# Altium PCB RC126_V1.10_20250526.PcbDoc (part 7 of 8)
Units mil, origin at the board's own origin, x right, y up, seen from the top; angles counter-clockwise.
Board outline 6299.62 x 3544.12 mil, 4 copper layers (Top, GND, Power, Bottom), stack 35.4 mil thick; 509 components, 417 nets, 1867 pads, 2150 vias.
Unrouted connection lines stored in the file: 1451.
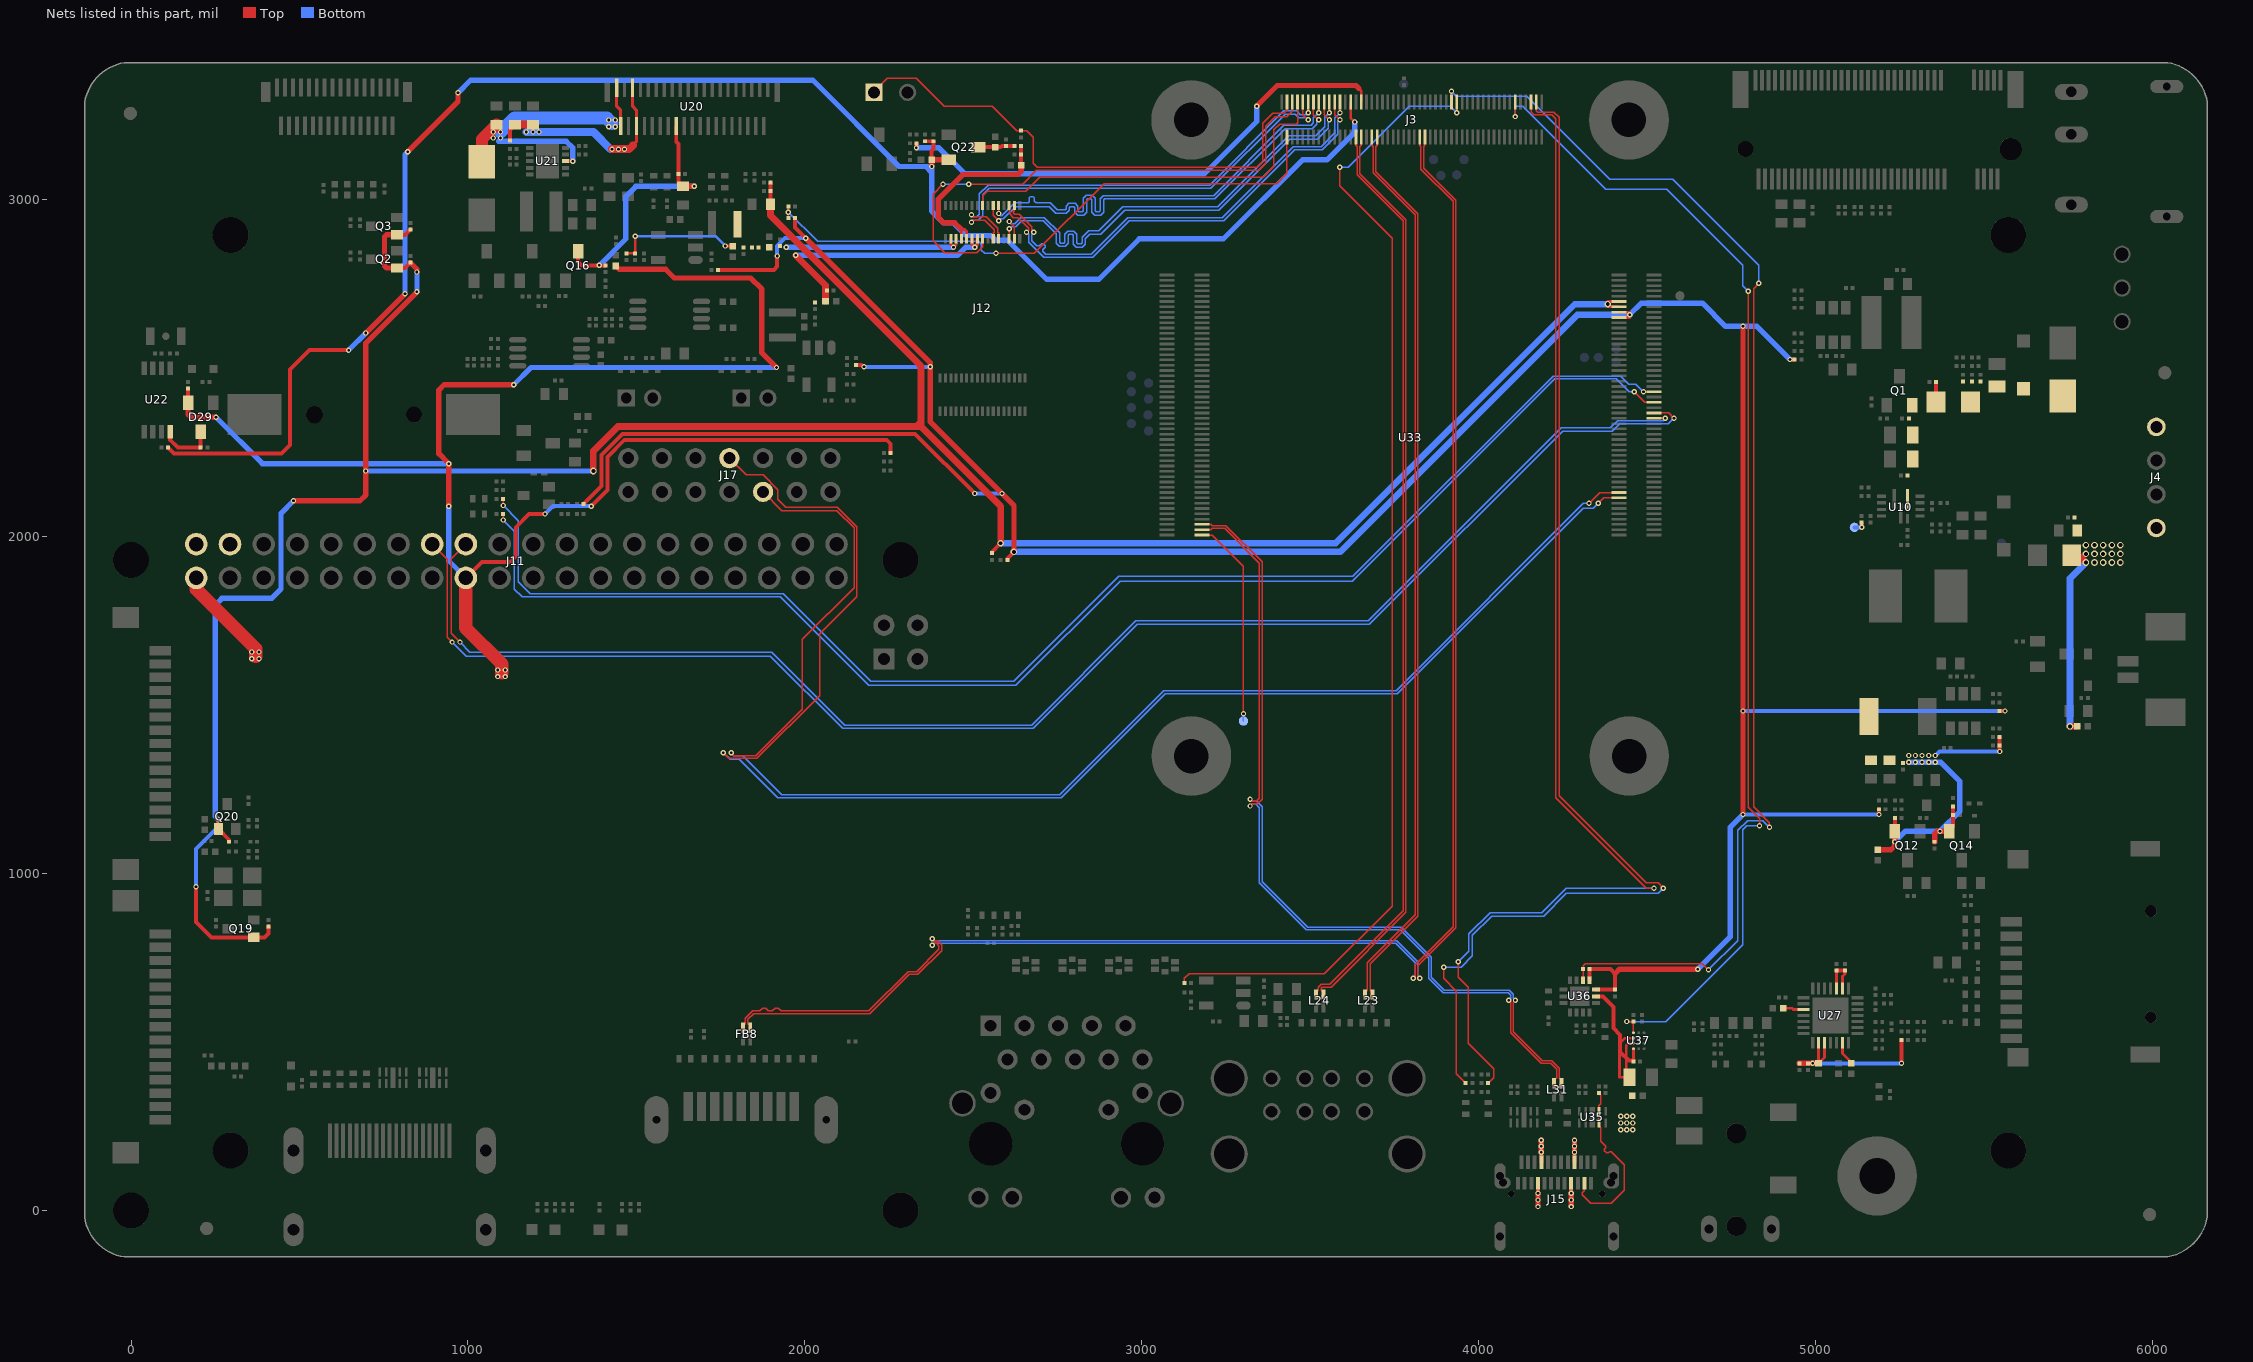
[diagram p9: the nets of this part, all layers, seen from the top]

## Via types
v1: diameter 15.75, hole 7.87, Top to Bottom, 2047 vias
v2: diameter 19.68, hole 11.81, Top to Bottom, 103 vias

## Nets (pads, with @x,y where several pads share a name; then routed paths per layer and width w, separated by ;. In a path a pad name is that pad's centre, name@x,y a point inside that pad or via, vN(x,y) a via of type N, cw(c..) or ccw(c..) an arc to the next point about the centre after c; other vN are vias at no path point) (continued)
TYPEC0TX2P: C254.2 J15.B2 U35.4 U35.7 | length 528.1
  Top w3.94: J15.B2@4312.99,80.71 4312.99,59.06 4307.09,53.15 4307.09,46.57 4332,21.65 4392.41,21.65 4431.1,60.35 4431.1,136.5 4392.63,174.98 4387.52,174.98 4383.5,170.96 4379.32,170.96 4372.36,177.92 4372.36,182.09 4376.85,186.58 4376.85,190.76 4362.2,205.4 4362.2,245.08 4356.29,250.99 U35.4@4356.29,260.34 U35.7@4356.29,294.78 4356.29,311.02 4362.2,316.93 4362.2,342.52 C254.2@4356.3,348.43
TYPEC5V_PWREN_H: J3.11 R355.1 U37.D3 | length 3514.4
  Top w3.94: v1(4107.48,3246.46) 4107.48,3279.1 J3.11@4107.48,3289.77 ; v1(4438.98,561.02) R355.1@4458.66,561.02 U37.D3@4458.66,527.56 ; v1(4799.21,2728.35) 4799.21,1196.85 4832.68,1163.39 v1(4832.68,1141.73)
  Bottom w3.94: v1(4107.48,3246.46) 4107.48,3273.62 4111.42,3277.56 4129.92,3277.56 4375.98,3031.5 4557.09,3031.5 4783.46,2805.12 4783.46,2744.09 v1(4799.21,2728.35) ; v1(4438.98,561.02) 4555.12,561.02 4783.46,789.37 4783.46,1129.92 4795.28,1141.73 v1(4832.68,1141.73)
TYPEC_DPTX_AUX_PUPDCTL1: J3.5 R338.1 | length 3640.9
  Top w3.94: v1(3938.98,738.19) 3938.98,692.91 3968.5,663.39 3968.5,496.06 4043.31,421.26 4043.31,393.7 R338.1@4027.56,377.95 ; J3.5@4154.72,3279.5 4154.72,3259.84 4162.6,3251.97 4216.54,3251.97 4228.35,3240.16 4228.35,1224.41 4496.06,956.69 v1(4519.68,956.69) ; J3.5@4154.73,3279.5 J3.5@4154.73,3289.77
  Bottom w3.94: v1(3938.98,738.19) 3970.47,769.69 3970.47,820.87 4033.46,883.86 4187.01,883.86 4259.84,956.69 v1(4519.68,956.69)
TYPEC_DPTX_AUX_PUPDCTL2: J3.3 R339.1 | length 3693.8
  Top w3.94: v1(3895.67,722.44) 3895.67,688.98 3933.07,651.57 3933.07,405.51 R339.1@3960.63,377.95 ; J3.3@4170.47,3279.9 4170.47,3263.78 4174.41,3259.84 4222.44,3259.84 4238.19,3244.09 4238.19,1230.32 4496.06,972.44 4531.5,972.44 v1(4547.24,956.69) ; J3.3@4170.48,3279.9 J3.3@4170.48,3289.77
  Bottom w3.94: v1(3895.67,722.44) 3946.85,722.44 3980.32,755.91 3980.32,816.93 4037.4,874.02 4192.91,874.02 4259.84,940.94 4531.5,940.94 v1(4547.24,956.69)
UART0_RX_M0_DEBUG: R274.2 U33.51 | length 4142.5
  Top w3.94: v1(1104.33,2049.21) R274.2@1104.33,2066.93 ; v1(4461.02,2429.92) 4492.52,2398.43 U33.51@4520.08,2398.43
  Bottom w3.94: v1(1104.33,2049.21) 1137.8,2015.75 1137.8,1844.49 1161.42,1820.87 1927.17,1820.87 2188.98,1559.06 2625.98,1559.06 2935.04,1868.11 3624.02,1868.11 4224.41,2468.5 4407.48,2468.5 4446.06,2429.92 v1(4461.02,2429.92)
UART0_TX_M0_DEBUG: R273.2 U33.55 | length 4152
  Top w3.94: v1(1104.33,2092.52) R273.2@1104.33,2112.2 ; v1(4488.19,2429.92) U33.55@4520.08,2429.92
  Bottom w3.94: v1(1104.33,2092.52) 1149.61,2047.24 1149.61,1865.98 1184.87,1830.71 1935.04,1830.71 2194.88,1570.87 2620.08,1570.87 2931.1,1881.89 3626.27,1881.89 4220.76,2476.38 4420.43,2476.38 4444.05,2452.76 4465.35,2452.76 v1(4488.19,2429.92)
UART5_RX_M0_1V8: J17.8 U33.16 | length 4476.2
  Top w3.94: v1(1757.87,1358.27) 1773.62,1342.52 1857.59,1342.52 2043.31,1528.23 2043.31,1711.92 2153.54,1822.16 2153.54,2028.85 2095.78,2086.61 1943.59,2086.61 1919.29,2110.91 1919.29,2139.75 1875.97,2183.07 1825.2,2183.07 J17.8@1775.59,2232.68 ; v1(4354.33,2099.21) 4370.08,2114.96 U33.16@4415.35,2114.96
  Bottom w3.94: v1(1757.87,1358.27) 1777.56,1338.58 1805.12,1338.58 1919.29,1224.41 2759.84,1224.41 3068.9,1533.46 3757.87,1533.46 4309.06,2084.65 4339.76,2084.65 v1(4354.33,2099.21)
UART5_TX_M0_1V8: J17.9 U33.18 | length 4243
  Top w3.94: v1(1781.5,1358.27) 1789.37,1350.39 1854.33,1350.39 1992.13,1488.19 1992.13,1694.88 2145.67,1848.43 2145.67,2025.59 2094.49,2076.77 1931.5,2076.77 J17.9@1875.59,2132.68 ; v1(4326.77,2099.21) 4358.27,2130.71 U33.18@4415.35,2130.71
  Bottom w3.94: v1(1781.5,1358.27) 1789.37,1350.39 1814.96,1350.39 1931.1,1234.25 2755.91,1234.25 3064.96,1543.31 3753.94,1543.31 4309.84,2099.21 v1(4326.77,2099.21)
UART7_RX_M0: J11.18 U33.45 | length 4407.7
  Top w3.94: v1(976.38,1687.01) 950.79,1712.6 950.79,1934.65 J11.18@993.7,1977.56 ; U33.45@4520.08,2351.18 v1(4553.15,2351.18)
  Bottom w3.94: v1(976.38,1687.01) 1005.91,1657.48 1901.57,1657.48 2118.11,1440.94 2673.23,1440.94 2982.28,1750 3671.26,1750 4244.09,2322.83 4389.76,2322.83 4411.42,2344.49 4546.46,2344.49 v1(4553.15,2351.18)
UART7_TX_M0: J11.16 U33.47 | length 4493.3
  Top w3.94: J11.16@893.7,1977.56 938.98,1932.28 938.98,1700.79 v1(952.76,1687.01) ; U33.47@4520.08,2366.93 4562.99,2366.93 v1(4578.74,2351.18)
  Bottom w3.94: v1(952.76,1687.01) 994.09,1645.67 1897.64,1645.67 2112.2,1431.1 2677.17,1431.1 2986.22,1740.16 3675.2,1740.16 4248.03,2312.99 4395.67,2312.99 4417.32,2334.65 4562.2,2334.65 v1(4578.74,2351.18)
UFS_FSPI_PLUG: J2.1 J3.97 R15.1 | length 1558.8
  Top w3.94: J2.1@2204.72,3318.5 2204.72,3320.87 2244.09,3360.24 2330.71,3360.24 2413.39,3277.56 2555.12,3277.56 2627.95,3204.72 R15.1@2641.73,3204.72 2657.48,3204.72 2677.17,3185.04 2677.17,3108.27 2688.98,3096.46 3340.55,3096.46 3358.27,3114.17 3358.27,3226.38 3387.8,3255.91 3421.26,3255.91 3430.32,3264.96 3430.32,3279.8 J3.97@3430.32,3289.77
UFS_REFCLK: J3.93 J12.42 | length 1178.7
  Top w3.94: J12.42@2527.17,2982.28 2527.17,3011.81 2540.94,3025.59 2655.51,3025.59 2696.85,3066.93 3360.24,3066.93 3391.73,3098.43 3391.73,3206.69 3409.45,3224.41 3457.87,3224.41 3461.81,3228.35 3461.81,3279.8 J3.93@3461.82,3289.77
UFS_RSTN: J3.95 J12.57 | length 1591.5
  Top w3.94: v1(2409.45,3045.28) 2379.92,3015.75 2379.92,2877.95 2415.35,2842.52 2509.84,2842.52 2527.17,2859.84 J12.57@2527.17,2883.86 ; v1(2486.22,3045.28) 2645.67,3045.28 2687.01,3086.61 3346.46,3086.61 3368.11,3108.27 3368.11,3218.5 3395.67,3246.06 3430.32,3246.06 3446.06,3261.81 3446.06,3278.3 J3.95@3446.07,3289.77
  Bottom w3.94: v1(2409.45,3045.28) v1(2486.22,3045.28)
UFS_RX_D0N: J3.83 J12.62 | length 1334.3
  Top w3.94: J12.62@2605.91,2883.86 2605.91,2913.39 v1(2606.3,2913.39) ; J3.83@3540.56,3289.77 3540.55,3252.36 v1(3556.3,3236.61)
  Bottom w3.94: v1(2606.3,2913.39) 2612.2,2919.29 2625.98,2919.29 2643.7,2937.01 2706.69,2937.01 2745.6,2898.11 2745.6,2869.94 2754.31,2861.22 2772.31,2861.22 2781.03,2869.94 2781.03,2893.7 2783.98,2896.65 2793.82,2896.65 2796.78,2893.7 2796.78,2867.97 2805.49,2859.25 2823.49,2859.25 2832.21,2867.97 2832.21,2883.86 2845.47,2897.12 2877.44,2897.12 2948.82,2968.5 3228.49,2968.5 3439.12,3179.13 3519.69,3179.13 3552.17,3211.61 3552.17,3232.48 v1(3556.3,3236.61)
UFS_RX_D0P: J3.81 J12.63 | length 1343.1
  Top w3.94: v1(2606.3,2935.04) 2621.65,2919.69 J12.63@2621.65,2883.86 ; v1(3556.3,3258.27) J3.81@3556.3,3289.77
  Bottom w3.94: v1(2606.3,2935.04) 2612.2,2929.13 2621.91,2929.13 2639.62,2946.85 2639.76,2946.85 2710.77,2946.85 2755.44,2902.18 2755.44,2874.02 2758.39,2871.06 2768.23,2871.06 2771.19,2874.02 2771.19,2897.78 2779.9,2906.5 2797.9,2906.5 2806.62,2897.78 2806.62,2872.05 2809.57,2869.09 2819.41,2869.09 2822.37,2872.05 2822.37,2887.94 2841.4,2906.96 2871.53,2906.96 2942.91,2978.35 3224.41,2978.35 3435.04,3188.98 3515.61,3188.98 3542.32,3215.69 3542.32,3244.29 v1(3556.3,3258.27)
UFS_RX_D1N: J3.91 J12.59 | length 1344.8
  Top w3.94: v1(2494.09,2933.07) 2500,2938.98 2533.92,2938.98 2561.61,2911.28 2561.61,2902.56 2558.66,2899.61 J12.59@2558.66,2883.86 ; J3.91@3477.56,3289.77 3477.56,3252.36 v1(3493.31,3236.61)
  Bottom w3.94: v1(2494.09,2933.07) 2500,2938.98 2513.78,2938.98 2527.56,2952.76 2527.56,3013.78 2547.24,3033.46 3204.86,3033.46 3425.34,3253.94 3454.58,3253.94 3466,3242.52 3487.4,3242.52 v1(3493.31,3236.61)
UFS_RX_D1P: J3.89 J12.60 | length 1332.9
  Top w3.94: v1(2494.09,2954.72) 2500,2948.82 2537.99,2948.82 2571.46,2915.35 2571.46,2902.56 2574.41,2899.61 J12.60@2574.41,2883.86 ; v1(3493.31,3258.27) J3.89@3493.31,3289.77
  Bottom w3.94: v1(2494.09,2954.72) 2500,2948.82 2509.7,2948.82 2517.72,2956.83 2517.72,3015.75 2517.72,3017.86 2543.17,3043.31 3200.79,3043.31 3421.26,3263.78 3458.66,3263.78 3470.08,3252.36 3487.4,3252.36 v1(3493.31,3258.27)
UFS_TX_D0N: J3.79 J12.37 | length 1337.9
  Top w3.94: J12.37@2605.91,2982.28 2605.91,2966.54 2608.86,2963.58 2608.86,2956.69 2618.7,2946.85 2631.75,2946.85 2663.39,2915.21 2663.39,2909.45 v1(2657.48,2903.54) ; J3.79@3572.05,3289.76 3572.05,3252.36 v1(3587.8,3236.61)
  Bottom w3.94: v1(2657.48,2903.54) 2663.39,2897.64 2663.39,2873.88 2708.52,2828.74 2853.42,2828.74 2961.68,2937.01 3242.27,2937.01 3452.9,3147.64 3535.43,3147.64 3581.69,3193.9 3581.69,3230.51 v1(3587.8,3236.61)
UFS_TX_D0P: J3.77 J12.36 | length 1327.9
  Top w3.94: J12.36@2621.65,2982.28 2621.65,2966.54 2618.7,2963.58 2618.7,2960.77 2622.78,2956.69 2635.83,2956.69 2673.23,2919.29 2673.23,2909.45 v1(2679.13,2903.54) ; v1(3587.8,3258.27) J3.77@3587.8,3289.77
  Bottom w3.94: v1(2679.13,2903.54) 2673.23,2897.64 2673.23,2877.95 2688.01,2863.17 2695.91,2863.17 2702.4,2869.66 2706.57,2869.66 2713.53,2862.7 2713.53,2858.53 2706.17,2851.16 2706.17,2846.98 2714.57,2838.58 2849.34,2838.58 2957.61,2946.85 3238.19,2946.85 3448.82,3157.48 3531.36,3157.48 3571.85,3197.97 3571.85,3242.32 v1(3587.8,3258.27)
UFS_TX_D1N: J3.87 J12.40 | length 1346.4
  Top w3.94: J12.40@2558.66,2982.28 2558.66,2953.15 v1(2574.8,2937.01) ; J3.87@3509.06,3289.77 3509.06,3252.36 v1(3524.8,3236.61)
  Bottom w3.94: v1(2574.8,2937.01) 2580.71,2942.91 2588.58,2942.91 2625,2979.33 2724.34,2979.33 2744.02,2959.65 2775.73,2959.65 2784.45,2968.36 2784.45,2976.38 2787.4,2979.33 2797.24,2979.33 2800.2,2976.38 2800.2,2962.46 2808.92,2953.74 2826.91,2953.74 2835.63,2962.46 2835.63,3000 2838.58,3002.95 2848.43,3002.95 2851.38,3000 2851.38,2962.46 2860.1,2953.74 2878.09,2953.74 2886.81,2962.46 2886.81,2999.02 2889.76,3001.97 3216.68,3001.97 3425.34,3210.63 3505.91,3210.63 3518.7,3223.43 3518.7,3230.51 v1(3524.8,3236.61)
UFS_TX_D1P: J3.85 J12.39 | length 1330.7
  Top w3.94: J12.39@2574.41,2982.28 2574.8,2981.89 v1(2574.8,2958.66) ; v1(3524.8,3258.27) J3.85@3524.81,3289.77
  Bottom w3.94: v1(2574.8,2958.66) 2580.71,2952.76 2584.51,2952.76 2621.91,2990.16 2662.4,2990.16 2665.35,2993.11 2665.35,3006.34 2668.31,3009.29 2678.15,3009.29 2681.1,3006.34 2681.1,2994.65 2685.59,2990.16 2727.43,2990.16 2748.1,2969.49 2771.65,2969.49 2774.61,2972.44 2774.61,2980.45 2783.32,2989.17 2801.32,2989.17 2810.04,2980.45 2810.04,2966.54 2812.99,2963.58 2822.83,2963.58 2825.79,2966.54 2825.79,3004.08 2834.51,3012.8 2852.5,3012.8 2861.22,3004.08 2861.22,2966.54 2864.17,2963.58 2874.02,2963.58 2876.97,2966.54 2876.97,3003.09 2885.69,3011.81 3212.6,3011.81 3421.26,3220.47 3501.83,3220.47 3508.86,3227.5 3508.86,3242.32 v1(3524.8,3258.27)
USB2_OTG0_DM: L31.4 R343.1 U33.103 | length 2487.2
  Top w3.94: U33.103@3178.74,2020.47 3204.72,2020.47 3208.66,2024.41 3245.61,2024.41 3348.43,1921.6 3348.43,1223.73 3339.26,1214.57 3326.77,1214.57 v1(3320.87,1220.47) ; v1(4108.27,624.02) 4102.36,618.11 4102.36,530.82 4188.3,444.88 4215.86,444.88 4238.19,422.55 4238.19,394.69 4245.08,387.8 L31.4@4245.08,382.88 4244.09,382.88 R343.1@4244.09,368.11
  Bottom w3.94: v1(3320.87,1220.47) 3326.77,1214.57 3340.55,1214.57 3356.3,1198.82 3356.3,975.7 3491.45,840.55 3769.68,840.55 3858.27,751.97 3858.27,692.24 3896.96,653.54 4090.55,653.54 4102.36,641.73 4102.36,629.92 v1(4108.27,624.02)
USB2_OTG0_DP: L31.3 R345.1 U33.105 | length 2499.7
  Top w3.94: U33.105@3178.74,2036.22 3204.72,2036.22 3208.66,2032.28 3248.87,2032.28 3356.3,1924.86 3356.3,1220.47 3342.52,1206.69 3326.77,1206.69 v1(3320.87,1200.79) ; v1(4088.58,624.02) 4094.49,618.11 4094.49,527.56 4185.04,437.01 4212.6,437.01 4230.32,419.29 4230.32,394.69 4223.42,387.8 L31.3@4223.42,382.88 4224.41,381.89 R345.1@4224.41,368.11
  Bottom w3.94: v1(3320.87,1200.79) 3326.77,1206.69 3337.29,1206.69 3348.43,1195.56 3348.43,972.44 3488.19,832.68 3766.42,832.68 3850.39,748.71 3850.39,688.98 3893.7,645.67 4087.29,645.67 4094.49,638.47 4094.49,629.92 v1(4088.58,624.02)
USB2_OTG0_ID: P14.1 U33.101 | length 620
  Top w3.94: U33.101@3178.74,2004.72 3208.27,2004.72 3301.18,1911.81 v1(3301.18,1474.41)
  Bottom w3.94: P14.1@3301.18,1452.76 v1(3301.18,1474.41)
USB2_OTG0_VBUSDET: J3.98 R3.1 R4.1 | length 1782.1
  Top w3.94: R3.1@1950.79,2944.88 v1(1950.79,2962.6) R4.1@1950.79,2980.32 ; v1(2566.93,2840.55) 2681.1,2840.55 2887.8,3047.24 3399.61,3047.24 3430.32,3077.95 3430.32,3181 J3.98@3430.32,3185.83
  Bottom w3.94: v1(1950.79,2962.6) 2037.4,2875.98 2515.75,2875.98 2523.62,2868.11 2523.62,2850.39 2533.46,2840.55 v1(2566.93,2840.55)
USB20_1DM: FB8.1 J3.48 R282.2 | length 4844.1
  Top w3.94: R282.2@1816.93,533.46 1816.93,547.24 FB8.1@1815.94,548.23 1822.83,555.12 1822.83,570.53 1844.83,592.52 1866.14,592.52 1874.02,600.39 1883.86,600.39 1891.73,592.52 1903.54,592.52 1911.42,600.39 1921.26,600.39 1929.13,592.52 2189.65,592.52 2305.79,708.66 2331.38,708.66 2397.64,774.92 2397.64,786.11 2390.44,793.31 2383.86,793.31 v1(2377.95,787.4) ; v1(3805.12,688.98) 3811.02,694.88 3811.02,730.19 3923.23,842.4 3923.23,2994.77 3827.95,3090.05 3827.95,3157.48 3824.02,3161.42 3824.02,3180.9 J3.48@3824.02,3185.83
  Bottom w3.94: v1(2377.95,787.4) 2383.86,793.31 3752.64,793.31 3811.02,734.93 3811.02,694.88 v1(3805.12,688.98)
USB20_1DP: FB8.2 J3.46 R283.2 | length 4857.2
  Top w3.94: R283.2@1836.61,533.46 1836.61,547.24 FB8.2@1837.6,548.23 1830.71,555.12 1830.71,567.27 1848.09,584.65 2192.91,584.65 2309.06,700.79 2334.65,700.79 2405.51,771.65 2405.51,789.37 2393.7,801.18 2383.86,801.18 v1(2377.95,807.09) ; v1(3824.8,688.98) 3818.9,694.88 3818.9,726.93 3931.1,839.14 3931.1,2998.03 3835.83,3093.31 3835.83,3157.48 3839.76,3161.42 3839.76,3178 J3.46@3839.77,3185.83
  Bottom w3.94: v1(2377.95,807.09) 2383.86,801.18 3755.91,801.18 3818.9,738.19 3818.9,694.88 v1(3824.8,688.98)
USB20_2DM: J3.66 L23.1 R299.1 | length 2669.8
  Top w3.94: R299.1@3663.39,631.89 3663.39,646.66 L23.1@3662.4,646.66 3669.29,653.55 3669.29,735.54 3811.02,877.28 3811.02,2954.72 3686.22,3079.53 3686.22,3157.48 3682.28,3161.42 3682.28,3179.9 J3.66@3682.29,3185.83
USB20_2DP: J3.64 L23.2 R301.1 | length 2669.2
  Top w3.94: R301.1@3683.07,631.89 3683.07,645.67 L23.2@3684.06,646.66 3677.17,653.55 3677.17,732.28 3818.9,874.02 3818.9,2957.99 3694.09,3082.79 3694.09,3157.48 3698.03,3161.42 3698.03,3179.6 J3.64@3698.04,3185.83
USB20_3DM: J3.72 L24.1 R300.1 | length 2735.4
  Top w3.94: R300.1@3517.72,631.89 3517.72,646.66 L24.1@3516.73,646.66 3523.62,653.55 3523.62,661.42 3523.62,662.71 3532.17,671.26 3533.46,671.26 3557.76,671.26 3775.59,889.09 3775.59,2937.01 3638.98,3073.62 3638.98,3157.48 3635.04,3161.42 3635.04,3179.3 J3.72@3635.04,3185.83
USB20_3DP: J3.70 L24.2 R302.1 | length 2734.8
  Top w3.94: R302.1@3537.4,631.89 3537.4,645.67 L24.2@3538.39,646.66 3531.5,653.55 3531.5,659.45 3535.43,663.39 3561.02,663.39 3783.46,885.83 3783.46,2940.27 3646.85,3076.88 3646.85,3157.48 3650.79,3161.42 3650.79,3176.7 J3.70@3650.79,3185.83
USB_PWR_EN: J3.33 R279.2 | length 3438.3
  Top w3.94: R279.2@3125.98,675.2 3125.98,688.98 3139.76,702.76 3541.34,702.76 3742.13,903.54 3742.13,2885.83 3586.61,3041.34 v1(3586.61,3096.46) ; v1(3934.25,3258.27) 3934.25,3278.5 J3.33@3934.26,3289.77
  Bottom w3.94: v1(3586.61,3096.46) 3612.2,3096.46 3793.31,3277.56 3914.96,3277.56 v1(3934.25,3258.27)
USBCC_INT_L: J3.35 R351.2 U36.5 | length 3839.8
  Top w3.94: J3.35@3918.51,3289.77 3918.51,3300.8 v1(3918.5,3321.26) ; U36.5@4309.06,683.46 R351.2@4309.06,716.54 4309.06,726.38 4314.96,732.28 4663.39,732.28 v1(4681.1,714.57) ; v1(4830.71,2751.97) 4814.96,2736.22 4814.96,1198.82 4862.2,1151.57 v1(4862.2,1137.8)
  Bottom w3.94: v1(3918.5,3321.26) 3932.68,3307.09 4141.73,3307.09 4387.8,3061.02 4574.8,3061.02 4830.71,2805.12 v1(4830.71,2751.97) ; v1(4681.1,714.57) 4767.72,801.18 4767.72,1127.95 4797.24,1157.48 4842.52,1157.48 v1(4862.2,1137.8)
VBUS_TYPEC0: C256.1 J15.A4 J15.A9 J15.B4 J15.B9 R352.2 R353.1 U36.2 U37.A3 U37.B3 U37.C3 | length 863.3
  Top w7.87: R353.1@4458.66,442.91 4458.66,444.88 U37.A3@4458.66,480.32 ; U37.B3@4458.66,496.06 4442.91,496.06 4437.01,490.16 4437.01,415.35 4446.85,405.51 C256.1@4446.85,395.67 4417.32,395.67 4417.32,496.06 4433.07,511.81 U37.C3@4458.66,511.81
  Top w11.81: v1(4175.2,51.18) J15.B9@4175.2,80.71 ; J15.A4@4185.04,143.7 v1(4185.04,173.23) ; v1(4273.62,51.18) J15.B4@4273.62,80.71 ; J15.A9@4283.46,143.7 v1(4283.46,173.23) ; U36.2@4346.85,635.83 4368.11,635.83 4399.61,604.33 4399.61,541.34 4419.29,521.65 4419.29,470.47 4444.88,444.88 R353.1@4458.66,444.88
  Top w15.75: v1(4175.2,11.81) v1(4175.2,51.18) ; v1(4185.04,173.23) v1(4185.04,208.66) ; v1(4273.62,11.81) v1(4273.62,51.18) ; v1(4283.46,173.23) v1(4283.46,208.66)
  other v1: 4175.2,31.5 4273.62,31.5 4185.04,190.94 4283.46,190.94 4421.26,240.16 4438.98,240.16 4456.69,240.16 4421.26,259.84 4438.98,259.84 4456.69,259.84 4421.26,279.53 4438.98,279.53 4456.69,279.53
VCC1V2_UFS_VCCQ_S0: C237.1 C238.1 J12.51 J12.52 R328.2 | length 553.8
  Top w7.87: J12.51@2432.68,2883.86 2432.68,2866.54 v1(2440.94,2858.27) 2448.43,2865.75 J12.52@2448.43,2883.86
  Bottom w15.75: v1(1944.88,2858.27) v1(2440.94,2858.27)
VCC1V8_UFS_VCCQ2_S0: C229.1 C230.1 J12.53 J12.54 R320.2 | length 561
  Top w7.87: J12.53@2464.17,2883.86 2464.17,2911.42 2474.41,2911.42 2479.92,2905.91 J12.54@2479.92,2883.86
  Top w11.81: C229.1@2641.73,3102.36 C230.1@2641.73,3133.86 R320.2@2641.73,3159.45
  Top w15.75: 2464.17,2911.42 2444.49,2931.1 2411.42,2931.1 2395.67,2946.85 2395.67,3001.97 2468.5,3074.8 2631.89,3074.8 2641.73,3084.65 C229.1@2641.73,3102.36
VCC1V8_UFS_VCCQ2_S0_P: C209.1 C226.1 Q22.3 R320.1 | length 109.9
  Top w11.81: Q22.3@2513.78,3155.51 C209.1@2564.96,3155.51 2580.71,3155.51 2584.65,3159.45 C226.1@2596.46,3159.45 R320.1@2622.05,3159.45
VCC3V3_SYS: C156.1 C159.1 C160.1 C164.1 C173.1 D29.2 J11.1 J11.17 L15.2 Q12.2 Q14.2 R16.1 R164.2 R187.1 R206.2 R213.2 R220.2 R231.1 R254.1 | length 6563.5
  Top w3.94: v1(358.27,1637.8) 366.86,1646.39 368.11,1646.39 ; v1(358.27,1657.48) 358.27,1656.23 368.11,1646.39 ; 370.08,1644.98 372.74,1644.98 v1(379.92,1637.8) ; 370.08,1646.39 368.11,1646.39 ; 370.08,1648.62 378.93,1657.48 v1(379.92,1657.48) ; v1(1088.58,1584.65) 1089.84,1584.65 1100.39,1595.19 1100.39,1594.49 ; v1(1088.58,1604.33) 1100.39,1604.33
  Top w11.81: D29.2@169.29,2397.64 R16.1@169.29,2438.98 ; J11.17@993.7,1877.56 1041.34,1925.2 1125.98,1925.2 1141.73,1940.94 1141.73,2027.56 1181.1,2066.93 v1(1228.35,2066.93) ; v1(1366.14,2090.55) 1413.39,2137.8 1413.39,2236.22 1464.57,2287.4 2242.13,2287.4 2253.94,2275.59 R220.2@2253.94,2248.03 ; Q12.2@5234.25,1125.99 R206.2@5234.25,1165.35 ; Q14.2@5395.67,1125.99 5407.48,1137.8 R213.2@5407.48,1173.23 C173.1@5407.48,1198.82 ; v1(5545.28,1362.2) C160.1@5545.28,1379.92 R187.1@5545.28,1405.51
  Top w15.75: D29.2@169.29,2397.64 169.29,2362.2 177.17,2354.33 v1(251.97,2354.33) ; v1(942.91,2090.55) v1(942.91,2216.54) 913.39,2246.06 913.39,2435.04 929.13,2450.79 v1(1135.83,2450.79) ; R254.1@1438.98,2803.15 1448.82,2793.31 1586.61,2793.31 1612.2,2767.72 1838.58,2767.72 1872.05,2734.25 1872.05,2545.28 v1(1915.35,2501.97) ; R164.2@5183.07,1070.87 5222.44,1070.87 5234.25,1082.68 v1(5234.25,1094.49) Q12.2@5234.25,1125.99 ; R231.1@5352.36,1094.49 5352.36,1118.11 5360.24,1125.98 v1(5368.11,1125.98) Q14.2@5395.67,1125.99 Q14.2@5395.67,1114.17
  Top w39.37: J11.1@193.7,1877.56 193.7,1843.7 370.08,1667.32 370.08,1648.62 370.08,1646.39 370.08,1644.98 ; J11.17@993.7,1877.56 993.7,1728.74 1100.39,1622.05 1100.39,1604.33 1100.39,1595.19
  Bottom w11.81: v1(1228.35,2066.93) 1251.97,2090.55 v1(1366.14,2090.55) ; v1(5354.33,1350.39) 5366.14,1362.2 v1(5545.28,1362.2)
  Bottom w15.75: v1(251.97,2354.33) 389.76,2216.54 v1(942.91,2216.54) ; v1(942.91,2090.55) 942.91,1928.35 J11.17@993.7,1877.56 ; v1(1135.83,2450.79) 1187.01,2501.97 v1(1915.35,2501.97) ; v1(5234.25,1094.49) 5265.75,1125.98 v1(5368.11,1125.98) 5427.17,1185.04 5427.17,1273.62 5370.08,1330.71 v1(5354.33,1330.71) v1(5334.65,1330.71) v1(5314.96,1330.71) v1(5295.28,1330.71) v1(5275.59,1330.71)
  other v1: 5275.59,1350.39 5295.28,1350.39 5314.96,1350.39 5334.65,1350.39 1110.24,1584.65 1110.24,1604.33
VCC5V: C78.1 C79.1 FB9.1 J4.4 J11.2 J11.4 R18.2 | length 577.8
  Top w19.68: v2(5753.94,1437.01) FB9.1@5775.59,1437.01 ; R18.2@5759.84,1944.88 5779.53,1944.88 v2(5801.18,1923.23)
  Bottom w19.68: v2(5753.94,1437.01) 5753.94,1875.98 v2(5801.18,1923.23)
  other v2: 5826.77,1923.23 5852.36,1923.23 5877.95,1923.23 5903.54,1923.23 5801.18,1948.82 5826.77,1948.82 5852.36,1948.82 5877.95,1948.82 5903.54,1948.82 5801.18,1974.41 5826.77,1974.41 5852.36,1974.41 5877.95,1974.41 5903.54,1974.41
VCC12V: C83.1 C84.1 C89.1 J4.1 Q1.2 R1.1 R5.2 R17.2 U10.1 | length 59.1
  Top w11.81: R17.2@5356.3,2399.61 R1.1@5356.3,2458.66
VCC12V_DCIN: C155.1 C161.2 C162.1 D4.2 D5.2 R17.1 R176.2
VCC_1V8_S0: C178.1 C179.1 Q2.1 Q3.1 Q19.1 Q20.1 R9.2 R12.2 R212.2 R215.2 R233.1 R271.2 U33.88 U33.90 | length 8367.9
  Top w7.87: U33.88@4415.35,2681.89 4382.28,2681.89 v2(4382.28,2689.76) 4382.28,2697.64 U33.90@4415.35,2697.64
  Top w11.81: v1(192.91,960.63) 192.91,856.3 238.19,811.02 Q19.1@364.17,811.02 395.67,811.02 407.48,822.83 R212.2@407.48,842.52 ; Q20.1@259.84,1131.89 291.34,1100.4 R271.2@291.34,1094.49 ; Q2.1@789.37,2797.24 812.99,2797.24 R9.2@828.74,2812.99 ; Q3.1@789.37,2895.67 812.99,2895.67 R12.2@828.74,2911.42 ; C179.1@1897.64,2986.22 C178.1@1897.64,3025.59 R233.1@1897.64,3051.18 ; R215.2@2555.12,1950.79 2555.12,1954.72 v2(2580.71,1980.32)
  Top w15.75: Q20.1@259.84,1131.89 v1(259.84,1159.45) ; v1(482.28,2106.3) 679.13,2106.3 696.85,2124.02 v1(696.85,2194.88) 696.85,2574.8 v1(848.43,2726.38) ; Q2.1@789.37,2797.24 757.87,2797.24 751.97,2803.15 751.97,2889.76 757.87,2895.67 Q3.1@789.37,2895.67 ; R9.2@828.74,2812.99 848.43,2793.31 v1(848.43,2785.43)
  Top w19.68: v2(1372.05,2194.88) 1372.05,2253.94 1444.88,2326.77 2330.71,2326.77 ; C179.1@1897.64,2986.22 1897.64,2952.76 2344.49,2505.91 2344.49,2340.55 ; v2(2580.71,1980.32) 2580.71,2090.55 2344.49,2326.77 ; 2330.71,2326.77 2344.49,2340.55 ; 2330.71,2326.77 2344.49,2326.77 ; 2344.49,2326.77 2344.49,2340.55
  Bottom w11.81: v1(192.91,960.63) 192.91,1072.83 259.84,1139.76 v1(259.84,1159.45)
  Bottom w15.75: v1(259.84,1159.45) 250,1169.29 250,1797.24 269.69,1816.93 417.32,1816.93 444.88,1844.49 444.88,2068.9 v1(482.28,2106.3) ; v1(696.85,2194.88) v2(1372.05,2194.88) ; v1(848.43,2726.38) v1(848.43,2785.43)
  Bottom w19.68: v2(2580.71,1980.32) 3574.8,1980.32 4284.25,2689.76 v2(4382.28,2689.76)
VCC_1V8_S3: C227.1 C228.1 J3.73 Q22.2 R263.1 R321.1 | length 5152.8
  Top w3.94: J3.73@3619.3,3287.4 J3.73@3619.3,3289.77
  Top w7.87: J3.73@3619.29,3287.4 3619.29,3242.91 v1(3631.89,3230.32)
  Top w11.81: R263.1@110.24,2263.78 127.95,2246.06 446.85,2246.06 472.44,2271.65 472.44,2496.06 529.53,2553.15 v1(645.67,2553.15) ; C228.1@2356.3,3173.23 R321.1@2381.89,3173.23 2381.89,3150.59 2375.98,3144.69 C227.1@2375.98,3118.11
  Top w15.75: v1(696.85,2604.33) v1(812.99,2720.47) ; v1(820.87,3141.73) 970.47,3291.34 v1(970.47,3316.93) ; v1(2375.98,3098.43) C227.1@2375.98,3118.11 2395.67,3118.11 Q22.2@2427.16,3118.11
  Bottom w3.94: v1@2375.98,3096.46 v1(2375.98,3098.43)
  Bottom w15.75: v1(645.67,2553.15) v1(696.85,2604.33) ; v1(812.99,2720.47) 812.99,3133.86 v1(820.87,3141.73) ; v1(970.47,3316.93) 1007.87,3354.33 2023.62,3354.33 2279.53,3098.43 2358.27,3098.43 ; v1@2375.98,3096.46 2375.98,3080.71 ; v1(2375.98,3098.43) 2358.27,3098.43 ; v1(3631.89,3230.32) 3631.89,3200.79 3549.21,3118.11 3476.38,3118.11 3242.13,2883.86 2992.13,2883.86 2872.05,2763.78 2716.54,2763.78 2600.39,2879.92 2564.96,2879.92 2551.18,2893.7 2478.35,2893.7 2440.94,2931.1 2411.42,2931.1 2375.98,2966.54 2375.98,3080.71 ; 2358.27,3098.43 2375.98,3080.71
VCC_3V3_S0: C269.1 R3.2 R204.1 R214.2 R288.1 R303.1 R327.1 R331.1 R351.1 R357.1 U33.84 U33.86 U36.3 U36.4 | length 9721.1
  Top w7.87: U33.84@4415.35,2650.39 4447.24,2650.39 v1(4447.24,2658.27) 4447.24,2666.14 U33.86@4415.35,2666.14
  Top w11.81: R357.1@1342.52,2096.46 1395.67,2149.61 1395.67,2242.13 1458.66,2305.12 2326.77,2305.12 v1(2503.94,2127.95) ; R331.1@1742.13,2791.34 1907.48,2791.34 1917.32,2801.18 v1(1917.32,2832.68) ; R3.2@1970.47,2944.88 1970.47,2917.32 v1(2001.97,2885.83) ; R303.1@2151.57,2509.84 2167.32,2509.84 2173.23,2503.94 v1(2175.2,2503.94) ; R214.2@2600.39,1931.1 2600.39,1935.04 v2(2620.08,1954.72) ; U36.4@4328.74,683.46 R351.1@4328.74,716.54 4389.76,716.54 4403.54,702.76 C269.1@4403.54,655.51 U36.3@4346.85,655.51 ; v1(4923.23,2525.59) R288.1@4937.01,2525.59 ; v1(5187.01,1175.2) R327.1@5187.01,1190.94 ; R204.1@5545.28,1482.28 v1(5561.02,1482.28)
  Top w15.75: v1(2001.97,2885.83) 2372.05,2515.75 v1(2372.05,2503.94) 2372.05,2340.55 v1(2584.65,2127.95) 2620.08,2092.52 v2(2620.08,1954.72) ; 4403.54,702.76 4417.32,716.54 v1(4649.61,716.54) ; v1(4783.46,1175.2) v1(4783.46,1482.28) v1(4783.46,2624.02)
  Bottom w11.81: v1(1917.32,2832.68) 1917.32,2862.2 1940.94,2885.83 v1(2001.97,2885.83) ; v1(2175.2,2503.94) v1(2372.05,2503.94) ; v1(2503.94,2127.95) v1(2584.65,2127.95) ; v1(4783.46,1175.2) v1(5187.01,1175.2) ; v1(4783.46,1482.28) v1(5561.02,1482.28)
  Bottom w15.75: v1(4447.24,2658.27) 4481.89,2692.91 4663.39,2692.91 4732.28,2624.02 v1(4783.46,2624.02) 4824.8,2624.02 v1(4923.23,2525.59) ; v1(4649.61,716.54) 4746.06,812.99 4746.06,1137.8 v1(4783.46,1175.2)
  Bottom w19.68: v2(2620.08,1954.72) 3588.58,1954.72 4292.13,2658.27 v1(4447.24,2658.27)
VCC_LDO5V: P1.1 R181.1 | length 35.4
  Top w9.84: v1(5135.83,2027.56) R181.1@5135.83,2041.34
  Bottom w11.81: P1.1@5114.17,2027.56 v1(5135.83,2027.56)
VCC_LEDA2: C177.1 D24.2 U20.38 U20.39 U21.8 | length 916.5
  Top w9.84: U20.39@1440.94,3331.89 1440.94,3277.56 1452.76,3265.75 U20.38@1452.76,3218.71
  Top w11.81: U21.8@1289.37,3114.17 v1(1311.02,3114.17)
  Top w35.43: D24.2@1041.34,3112.2 1041.34,3179.13 C177.1@1084.65,3222.44
  Bottom w3.94: 1427.17,3226.38 v1(1437.01,3216.54)
  Bottom w15.75: v1(1096.46,3183.07) 1096.46,3179.13 1090.55,3173.23 1291.34,3173.23 1311.02,3153.54 v1(1311.02,3114.17)
  Bottom w39.37: v1(1096.46,3200.79) 1137.8,3242.13 1411.42,3242.13 1427.17,3226.38
  other v1: 1074.8,3183.07 1074.8,3200.79 1417.32,3216.54 1417.32,3236.22 1437.01,3236.22
VCC_LEDK2: R240.2 R244.1 R245.1 U20.34 U20.35 | length 688.4
  Top w3.94: R245.1@1191.56,3222.44 R245.1@1192.91,3222.44 v1(1192.91,3200.79) ; v1(1427.17,3149.61) v1@1427.41,3149.61
  Top w9.84: U20.35@1488.19,3331.89 1488.19,3277.56 1500,3265.75 U20.34@1500,3218.71 1500,3171.26 1490.16,3161.42
  Top w11.81: R240.2@1124.02,3175.2 1124.02,3206.69 R244.1@1139.76,3222.44
  Top w23.62: R244.1@1139.76,3222.44 R245.1@1191.56,3222.44 ; v1@1427.41,3149.61 v1(1446.85,3149.61) v1(1464.57,3149.61) 1478.35,3149.61 1490.16,3161.42
  Bottom w23.62: v1(1173.23,3200.79) v1(1192.91,3200.79) v1(1210.63,3200.79) 1372.05,3200.79 1423.23,3149.61 v1(1464.57,3149.61)
VCC_RTC: C188.1 D29.3 U22.8 | length 171.2
  Top w11.81: U22.8@116.14,2311.02 116.14,2287.4 139.76,2263.78 C188.1@206.69,2263.78 D29.3@206.69,2311.02
VCC_TP: C185.1 C186.1 Q16.3 R232.2 U20.24 | length 790.7
  Top w9.84: 1618.11,3171.26 U20.24@1618.11,3218.71
  Top w11.81: Q16.3@1326.77,2846.46 1326.77,2814.96 1336.61,2805.12 v1(1389.76,2805.12) R232.2@1407.48,2805.12 ; 1618.11,3171.26 1624.02,3165.35 C186.1@1624.02,3076.77 1624.02,3051.18 1625.98,3051.18 C185.1@1637.8,3039.37
  Top w15.75: C185.1@1637.8,3039.37 v1(1671.26,3039.37)
  Bottom w15.75: v1(1389.76,2805.12) 1468.5,2883.86 1468.5,3009.84 1498.03,3039.37 v1(1671.26,3039.37)
VCC_UFS1V2_S0_P: C239.1 C240.1 C242.1 L29.2 R328.1 R329.1 | length 428.9
  Top w7.87: R329.1@1470.47,2840.55 1494.86,2840.55 1496.06,2841.75 v1(1496.06,2891.73) C242.1@1496.06,2840.55 ; v1(1763.78,2862.2) C239.1@1785.43,2862.2
  Bottom w7.87: v1(1496.06,2891.73) 1734.25,2891.73 v1(1763.78,2862.2)
VCC_UFS_S0: C207.1 C208.1 J12.55 J12.56 R284.2 | length 771.5
  Top w9.84: J12.55@2495.67,2883.86 2495.67,2866.54 v1(2503.94,2858.27) 2511.42,2865.75 J12.56@2511.42,2883.86
  Top w19.68: v1(1972.44,2834.65) 2061.02,2746.06 C207.1@2061.02,2698.82
  Bottom w15.75: v1(1972.44,2834.65) 2452.76,2834.65 2476.38,2858.27 v1(2503.94,2858.27)
VCCA3V3_CODEC: C243.1 C244.1 FB15.2 R304.2 U27.16 U27.17 | length 519.1
  Top w7.87: C244.1@5007.87,437.01 5017.72,446.85 5025.59,454.72 U27.17@5025.59,498.03 ; C244.1@5007.87,437.01 U27.16@5007.88,498.03
  Top w11.81: v1(5253.94,437.01) R304.2@5253.94,505.91
  Top w15.75: FB15.2@4950.79,437.01 C243.1@4976.38,437.01 v1(4990.16,437.01) C244.1@5007.87,437.01
  Bottom w11.81: v1(4990.16,437.01) v1(5253.94,437.01)
VCCIO_CODEC: C236.1 FB14.2 U27.2 U27.3 | length 135.2
  Top w7.87: U27.3@5061.03,659.45 C236.1@5061.02,712.6 ; U27.2@5078.74,659.45 5078.74,694.88 5086.61,702.76 FB14.2@5086.61,712.6
  Top w11.81: C236.1@5061.02,712.6 FB14.2@5086.61,712.6
VDDA_1V2_S0: J3.69 R323.1 | length 1540.2
  Top w3.94: J3.69@3650.79,3289.77 J3.69@3650.79,3290.4
  Top w7.87: 3643.7,3329.92 3650.79,3322.83 J3.69@3650.79,3290.4
  Top w11.81: v1(2330.71,3153.54) R323.1@2330.71,3167.32
  Top w15.75: v1(3340.55,3277.56) 3401.57,3338.58 3635.04,3338.58 3643.7,3329.92
  Bottom w15.75: v1(2330.71,3153.54) 2397.64,3153.54 2474.41,3076.77 3185.04,3076.77 3340.55,3232.28 v1(3340.55,3277.56)
VMID_ES8388: C274.1 U27.20 | length 71.6
  Top w7.87: U27.20@5078.74,498.03 5078.74,466.54 5104.33,440.94 C274.1@5104.33,437.01
VREF_ES8388: C272.1 U27.10 | length 60.7
  Top w7.87: C272.1@4903.54,600.39 4929.14,600.39 4933.07,596.46 U27.10@4962.6,596.46
pads on no net: H1.1 H2.1 H3.1 H4.1 H5.1 H6.1 H7.1 H8.1 J6.21 J6.22 J8.14 J8.15 J12.2 J12.4 J12.6 J12.8 J12.10 J12.12 J12.15 J12.16 J12.19 J12.20 J12.21 J12.22 J12.23 J12.25 J12.27 J12.29 J12.31 J12.33 J12.44 J12.45 J12.47 J12.48 J15.H1 J15.H2 J23.3 J23.4 J25.1 J25.7 J25.8 J30.5 J30.6 J30.7 J30.8 J30.10 J30.11 J30.13 J30.17 J30.19 J30.20 J30.22 J30.23 J30.24 J30.25 J30.26 J30.28 J30.29 J30.30 J30.31 J30.32 J30.34 J30.35 J30.36 J30.37 J30.38 J30.40 J30.42 J30.44 J30.46 J30.48 J30.56 J30.58 J30.67 J30.68 J30.69 J30.76 J30.77 M1.1 M2.1 M3.1 M4.1 U10.4 U10.12 U20.3 U20.5 U20.36 U20.37 U21.1 U21.3 U21.6 U21.10 U27.9 U27.21 U27.22 U27.25 U37.D1 Y3.3

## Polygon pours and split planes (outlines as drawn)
GND on Power (solid, remove dead copper, pour order 12): 6084.65,2066.93 6084.65,1832.68 6188.98,1832.68 6188.98,3433.07 -163.39,3433.07 -163.39,-163.39 6188.98,-163.39 6188.98,1818.9 6084.65,1818.9 6084.65,1647.64 5929.13,1647.64 5929.13,773.62 5438.98,283.46 4478.35,283.46 4478.35,-31.5 4133.86,-31.5 4133.86,283.46 3208.66,283.46 3125.98,366.14 3125.98,590.55 2379.92,590.55 1726.38,1244.09 289.37,1244.09 289.37,1669.29 133.86,1669.29 133.86,2208.66 486.22,2208.66 486.22,3379.92 4883.86,3379.92 4883.86,3033.46 5047.24,3033.46 5047.24,2968.5 5147.64,2968.5 5295.28,3116.14 5604.33,3116.14 5604.33,3011.81 5513.78,3011.81 5435.04,2933.07 5435.04,2746.06 5655.51,2746.06 5655.51,3366.14 5982.28,3366.14 5982.28,3263.78 6104.33,3263.78 6104.33,2598.43 5665.35,2598.43 5665.35,2066.93
VCC3V3_SYS on Power (solid, remove dead copper, pour order 11): 297.24,1669.29 297.24,1251.97 1732.28,1251.97 2381.89,602.36 4937.01,602.36 5401.57,1066.93 5401.57,1645.67 4541.34,1645.67 4397.64,1789.37 4124.02,1789.37 3850.39,1515.75 2108.27,1515.75 1954.72,1669.29
+5V_INPUT on Power (solid, remove dead copper, pour order 9): 4874.02,590.55 4874.02,291.34 5435.04,291.34 5921.26,777.56 5921.26,1647.64 5413.39,1647.64 5413.39,1064.96 4938.98,590.55
VBUS_TYPEC0 on Power (solid, remove dead copper, pour order 8): 4470.47,287.4 4141.73,287.4 4141.73,-23.62 4470.47,-23.62
3V3_PCIE on Power (solid, remove dead copper, pour order 7): 5039.37,3025.59 4883.86,3025.59 4883.86,2746.06 5427.17,2746.06 5427.17,2937.01 5509.84,3019.69 5596.46,3019.69 5596.46,3108.27 5301.18,3108.27 5153.54,2960.63 5039.37,2960.63
GND on Power (solid, remove dead copper, pour order 6): 6188.98,1809.06 6188.98,1848.43 6084.65,1848.43 6084.65,1809.06
VCC5V on Power (solid, remove dead copper, pour order 5): 6074.8,2059.06 5663.39,2059.06 5663.39,1923.23 5220.47,1923.23 5220.47,2318.9 3984.25,2318.9 3712.6,2047.24 2625.98,2047.24 2411.42,2261.81 1417.32,2261.81 1356.3,2200.79 141.73,2200.79 141.73,1677.17 1960.63,1677.17 2114.17,1523.62 3842.52,1523.62 4116.14,1797.24 4405.51,1797.24 4547.24,1655.51 6074.8,1655.51
+5V_INPUT on Power (solid, remove dead copper, pour order 4): 3133.86,590.55 3133.86,370.08 3212.6,291.34 4976.38,291.34 4976.38,590.55
+5V_INPUT on Power (solid, remove dead copper, pour order 2): 5655.51,2738.19 4875.98,2738.19 4875.98,3374.02 494.09,3374.02 494.09,2208.66 1348.43,2208.66 1409.45,2269.69 2417.32,2269.69 2631.89,2055.12 3708.66,2055.12 3980.32,2326.77 5230.32,2326.77 5230.32,1931.1 5655.51,1931.1
N38162991 on Power (solid, remove dead copper, pour order 0): 5974.41,3358.27 5665.35,3358.27 5665.35,2606.3 6096.46,2606.3 6096.46,3255.91 5974.41,3255.91
GND on GND (solid, remove dead copper, pour order 1): -155.51,3425.2 -155.51,-155.51 6181.1,-155.51 6181.1,3425.2
GND on Bottom (solid, remove dead copper, pour order 3): -171.26,3440.94 -171.26,-171.26 6196.85,-171.26 6196.85,3440.94
GND on Top (solid, remove dead copper, pour order 10): -147.64,3417.32 -147.64,-147.64 6173.23,-147.64 6173.23,3417.32

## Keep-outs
Top:
  region: 696.85,1777.56 740.16,1777.56 740.16,1793.31 696.85,1793.31 696.85,1777.56
  region: 1407.48,3151.57 1415.35,3151.57 1415.35,3187.01 1407.48,3187.01 1407.48,3151.57
  region: 1135.83,2832.68 1135.83,2870.08 1114.17,2870.08 1114.17,2832.68 1135.83,2832.68
  region: 5488.19,1403.54 5517.72,1403.54 5517.72,1411.42 5488.19,1411.42 5488.19,1403.54
  region: 799.21,2968.5 799.21,2960.63 842.52,2960.63 842.52,2968.5 799.21,2968.5
  region: 1301.18,2702.76 1301.18,2677.17 1305.12,2677.17 1305.12,2702.76 1301.18,2702.76
  region: 1730.32,2874.02 1763.78,2874.02 1763.78,2879.92 1730.32,2879.92 1730.32,2874.02
  region: 683.07,3027.56 812.99,3027.56 812.99,3041.34 683.07,3041.34 683.07,3027.56
  region: 1224.41,2055.12 1301.18,2055.12 1301.18,2059.06 1224.41,2059.06 1224.41,2055.12
  region: 1127.95,1627.95 1127.95,1710.63 1120.08,1710.63 1120.08,1627.95 1127.95,1627.95
  region: 5088.58,2923.23 5088.58,2913.39 5114.17,2913.39 5114.17,2923.23 5088.58,2923.23
  region: 3954.72,92.52 3960.63,92.52 3960.63,173.23 3954.72,173.23 3954.72,92.52
  region: 2913.39,598.43 2913.39,590.55 2990.16,590.55 2990.16,598.43 2913.39,598.43
  region: 1311.02,2783.46 1314.96,2783.46 1314.96,2820.87 1311.02,2820.87 1311.02,2783.46
  region: 1003.94,2665.35 1003.94,2681.1 994.09,2681.1 994.09,2665.35 1003.94,2665.35
  region: 5368.11,1059.06 5368.11,1066.93 5271.65,1066.93 5271.65,1059.06 5368.11,1059.06
  region: 2222.44,2972.44 2222.44,2990.16 2120.08,2990.16 2120.08,2972.44 2222.44,2972.44
  region: 3224.41,2728.35 3224.41,2596.46 3236.22,2596.46 3236.22,2728.35 3224.41,2728.35
  region: 1108.27,3088.58 1108.27,3094.49 1084.65,3094.49 1084.65,3088.58 1108.27,3088.58
  region: 1025.59,2781.5 1114.17,2781.5 1114.17,2791.34 1025.59,2791.34 1025.59,2781.5
  region: 1179.13,2338.58 1179.13,2330.71 1214.57,2330.71 1214.57,2338.58 1179.13,2338.58
  region: 1712.6,1478.35 1801.18,1478.35 1801.18,1484.25 1712.6,1484.25 1712.6,1478.35
  region: 4472.44,234.25 4468.5,234.25 4468.5,165.35 4472.44,165.35 4472.44,234.25
  region: 5192.91,2553.15 5265.75,2553.15 5265.75,2718.5 5192.91,2718.5 5192.91,2553.15
  region: 1208.66,1655.51 1246.06,1655.51 1246.06,1669.29 1208.66,1669.29 1208.66,1655.51
  region: 4222.44,1088.58 4175.2,1088.58 4175.2,1076.77 4222.44,1076.77 4222.44,1088.58
  region: 4263.78,671.26 4263.78,600.39 4334.65,600.39 4334.65,671.26 4263.78,671.26
  region: 3974.41,291.34 4011.81,291.34 4011.81,301.18 3974.41,301.18 3974.41,291.34
  region: 1547.24,2875.98 1547.24,2881.89 1494.09,2881.89 1494.09,2875.98 1547.24,2875.98
  region: 572.83,3281.5 527.56,3281.5 527.56,3279.53 572.83,3279.53 572.83,3281.5
  region: 5415.35,777.56 5415.35,889.76 5397.64,889.76 5397.64,777.56 5415.35,777.56
  region: 1797.24,3001.97 1783.46,3001.97 1783.46,2966.54 1797.24,2966.54 1797.24,3001.97
  region: 1362.2,2531.5 1370.08,2531.5 1370.08,2576.77 1362.2,2576.77 1362.2,2531.5
  region: 5828.74,1639.76 5828.74,1588.58 5840.55,1588.58 5840.55,1639.76 5828.74,1639.76
  region: 2907.48,411.42 3000,411.42 3000,421.26 2907.48,421.26 2907.48,411.42
  region: 1281.5,3068.9 1194.88,3068.9 1194.88,3066.93 1281.5,3066.93 1281.5,3068.9
  region: 122.05,683.07 122.05,673.23 167.32,673.23 167.32,683.07 122.05,683.07
  region: 588.58,3246.06 773.62,3246.06 773.62,3257.87 588.58,3257.87 588.58,3246.06
  region: 1246.06,1604.33 1285.43,1604.33 1285.43,1612.2 1246.06,1612.2 1246.06,1604.33
  region: 5224.41,2454.72 5224.41,2413.39 5240.16,2413.39 5240.16,2454.72 5224.41,2454.72
  region: 5157.48,1694.88 5456.69,1694.88 5456.69,1954.72 5157.48,1954.72 5157.48,1694.88
  region: 127.95,2517.72 127.95,2507.87 242.13,2507.87 242.13,2517.72 127.95,2517.72
  region: 303.15,726.38 303.15,685.04 401.57,685.04 401.57,726.38 303.15,726.38
  region: 909.45,1704.72 942.91,1704.72 942.91,1708.66 909.45,1708.66 909.45,1704.72
  region: 1200.79,3068.9 1202.76,3068.9 1202.76,3196.85 1200.79,3196.85 1200.79,3068.9
  region: 1350.39,2940.94 1350.39,3023.62 1346.46,3023.62 1346.46,2940.94 1350.39,2940.94
  region: 4935.04,435.04 4948.82,435.04 4948.82,521.65 4935.04,521.65 4935.04,435.04
  region: 5375.98,1261.81 5332.68,1261.81 5332.68,1234.25 5375.98,1234.25 5375.98,1261.81
  region: 4590.55,405.51 4590.55,372.05 4600.39,372.05 4600.39,405.51 4590.55,405.51
  region: 1610.24,1498.03 1610.24,1505.91 1547.24,1505.91 1547.24,1498.03 1610.24,1498.03
  region: 1234.25,2848.43 1234.25,2872.05 1232.28,2872.05 1232.28,2848.43 1234.25,2848.43
  region: 2604.33,411.42 2797.24,411.42 2797.24,423.23 2604.33,423.23 2604.33,411.42
  region: 1352.36,1551.18 1352.36,1584.65 1348.43,1584.65 1348.43,1551.18 1352.36,1551.18
  region: 624.02,3029.53 624.02,2942.91 635.83,2942.91 635.83,3029.53 624.02,3029.53
  region: 5456.69,1059.06 5456.69,1104.33 5446.85,1104.33 5446.85,1059.06 5456.69,1059.06
  region: 4553.15,370.08 4553.15,342.52 4657.48,342.52 4657.48,370.08 4553.15,370.08
  region: 1190.94,2122.05 1190.94,2179.13 1175.2,2179.13 1175.2,2122.05 1190.94,2122.05
  region: 698.82,3029.53 688.98,3029.53 688.98,2948.82 698.82,2948.82 698.82,3029.53
  region: 2374.02,1635.83 2338.58,1635.83 2338.58,1407.48 2374.02,1407.48 2374.02,1635.83
  region: 1149.61,1671.26 1149.61,1681.1 1112.2,1681.1 1112.2,1671.26 1149.61,1671.26
  region: 1188.98,2903.54 1269.68,2903.54 1269.68,3051.18 1188.98,3051.18 1188.98,2903.54
  region: 1555.12,3190.94 1555.12,3183.07 1592.52,3183.07 1592.52,3190.94 1555.12,3190.94
  region: 1407.48,2015.75 1407.48,2013.78 1482.28,2013.78 1482.28,2015.75 1407.48,2015.75
  region: 1716.54,2687.01 1716.54,2655.51 1722.44,2655.51 1722.44,2687.01 1716.54,2687.01
  region: 1667.32,3246.06 1866.14,3246.06 1866.14,3253.94 1667.32,3253.94 1667.32,3246.06
  region: 5137.8,1566.93 5137.8,1366.14 5350.39,1366.14 5350.39,1566.93 5137.8,1566.93
  region: 5395.67,1458.66 5368.11,1458.66 5368.11,1448.82 5395.67,1448.82 5395.67,1458.66
  region: 1153.54,2789.37 1153.54,2783.46 1224.41,2783.46 1224.41,2789.37 1153.54,2789.37
  region: 1151.57,2100.39 1151.57,2108.27 1114.17,2108.27 1114.17,2100.39 1151.57,2100.39
  region: 5104.33,2659.45 5139.76,2659.45 5139.76,2665.35 5104.33,2665.35 5104.33,2659.45
  region: 5391.73,1240.16 5360.24,1240.16 5360.24,1232.28 5391.73,1232.28 5391.73,1240.16
  region: 627.95,3305.12 627.95,3303.15 732.28,3303.15 732.28,3305.12 627.95,3305.12
  region: 1450.79,1559.06 1494.09,1559.06 1494.09,1568.9 1450.79,1568.9 1450.79,1559.06
  region: 1157.48,1673.23 1192.91,1673.23 1192.91,1679.13 1157.48,1679.13 1157.48,1673.23
  region: 600.39,1791.34 698.82,1791.34 698.82,1809.06 600.39,1809.06 600.39,1791.34
  region: 5295.28,2098.43 5287.4,2098.43 5287.4,2057.09 5295.28,2057.09 5295.28,2098.43
  region: 181.1,2106.3 181.1,2102.36 222.44,2102.36 222.44,2106.3 181.1,2106.3
  region: 4598.43,2775.59 4598.43,2757.87 4698.82,2757.87 4698.82,2775.59 4598.43,2775.59
  region: 1679.13,3305.12 1679.13,3291.34 1844.49,3291.34 1844.49,3305.12 1679.13,3305.12
  region: 1149.61,3125.98 1149.61,3090.55 1157.48,3090.55 1157.48,3125.98 1149.61,3125.98
  region: 446.85,2307.09 446.85,2259.84 454.72,2259.84 454.72,2307.09 446.85,2307.09
  region: 4431.1,2927.17 4431.1,2868.11 4456.69,2868.11 4456.69,2927.17 4431.1,2927.17
  region: 748.03,1751.97 789.37,1751.97 789.37,1755.91 748.03,1755.91 748.03,1751.97
  region: 177.17,633.86 177.17,566.93 185.04,566.93 185.04,633.86 177.17,633.86
  region: 5196.85,2419.29 5171.26,2419.29 5171.26,2411.42 5196.85,2411.42 5196.85,2419.29
  region: 2374.02,1736.22 2358.27,1736.22 2358.27,1637.8 2374.02,1637.8 2374.02,1736.22
  region: 1807.09,1462.6 1842.52,1462.6 1842.52,1476.38 1807.09,1476.38 1807.09,1462.6
  region: 3200.79,2773.62 3220.47,2773.62 3220.47,2775.59 3200.79,2775.59 3200.79,2773.62
  region: 4503.94,541.34 4444.88,541.34 4444.88,466.54 4503.94,466.54 4503.94,541.34
  region: 1604.33,2194.88 1604.33,2198.82 1519.68,2198.82 1519.68,2194.88 1604.33,2194.88
  region: 5122.05,2118.11 5122.05,2059.06 5131.89,2059.06 5131.89,2118.11 5122.05,2118.11
  region: 1692.91,2988.19 1692.91,2956.69 1702.76,2956.69 1702.76,2988.19 1692.91,2988.19
  region: 1852.36,1980.32 1862.2,1980.32 1862.2,2064.96 1852.36,2064.96 1852.36,1980.32
  region: 5338.58,2043.31 5330.71,2043.31 5330.71,2007.87 5338.58,2007.87 5338.58,2043.31
  region: 1413.39,2956.69 1413.39,2948.82 1454.72,2948.82 1454.72,2956.69 1413.39,2956.69
  region: 5488.19,694.88 5501.97,694.88 5501.97,781.5 5488.19,781.5 5488.19,694.88
  region: 1372.05,2338.58 1372.05,2281.5 1381.89,2281.5 1381.89,2338.58 1372.05,2338.58
Bottom:
  region: 3003.94,2133.86 3003.94,2222.44 2958.66,2222.44 2958.66,2133.86 3003.94,2133.86
  region: 3415.35,3253.94 3415.35,3218.5 3464.57,3218.5 3464.57,3253.94 3415.35,3253.94
  region: 194.88,340.55 206.69,340.55 206.69,358.27 194.88,358.27 194.88,340.55
  region: 5395.67,881.89 5344.49,881.89 5344.49,864.17 5395.67,864.17 5395.67,881.89
  region: 3161.42,2301.18 3151.57,2301.18 3151.57,2259.84 3161.42,2259.84 3161.42,2301.18
  region: 5287.4,895.67 5287.4,816.93 5303.15,816.93 5303.15,895.67 5287.4,895.67
  region: 3013.78,2679.13 3013.78,2608.27 3108.27,2608.27 3108.27,2679.13 3013.78,2679.13
  region: 2523.62,2966.54 2840.55,2966.54 2840.55,3029.53 2523.62,3029.53 2523.62,2966.54
  region: 3161.42,2637.8 3161.42,2555.12 3236.22,2555.12 3236.22,2637.8 3161.42,2637.8
  region: 730.31,3192.91 730.31,2931.1 763.78,2931.1 763.78,3192.91 730.31,3192.91
  region: 4427.17,2736.22 4427.17,2769.69 4413.39,2769.69 4413.39,2736.22 4427.17,2736.22
  region: 2692.91,2907.48 2692.91,2901.57 2744.09,2901.57 2744.09,2907.48 2692.91,2907.48
  region: 3187.01,2501.97 3187.01,2460.63 3240.16,2460.63 3240.16,2501.97 3187.01,2501.97
  region: 4553.15,2773.62 4553.15,2769.69 4675.2,2769.69 4675.2,2773.62 4553.15,2773.62
  region: 2667.32,2980.32 2667.32,2946.85 2722.44,2946.85 2722.44,2980.32 2667.32,2980.32
  region: 994.09,2696.85 994.09,2657.48 1023.62,2657.48 1023.62,2696.85 994.09,2696.85
  region: 3198.82,2393.7 3198.82,2348.43 3267.72,2348.43 3267.72,2393.7 3198.82,2393.7
  region: 45.28,328.74 45.28,314.96 124.02,314.96 124.02,328.74 45.28,328.74
  region: 1206.69,2655.51 1206.69,2580.71 2862.2,2580.71 2862.2,2655.51 1206.69,2655.51
  region: 3346.46,2334.65 3346.46,2519.69 3257.87,2519.69 3257.87,2334.65 3346.46,2334.65
  region: 6049.21,2675.2 5907.48,2675.2 5907.48,2661.42 6049.21,2661.42 6049.21,2675.2
  region: 5305.12,761.81 5375.98,761.81 5375.98,783.46 5305.12,783.46 5305.12,761.81
Keep-Out Layer:
  lines w3.94: -137.8,-19.29 -137.8,3288.58 ; -137.8,-19.23 ccw(c-0.02,0.38) -19.63,-137.41 ; -137.79,3288.63 cw(c4.92,3263.98) -19.73,3406.69 ; -19.69,-137.4 6043.7,-137.4 ; -19.69,3406.69 6043.7,3406.69 ; 6043.62,3406.71 cw(c6020.78,3265.66) 6161.78,3288.75 ; 6043.67,-137.41 ccw(c6017.43,6.98) 6161.82,-19.26 6161.81,3288.58 ; 5972.44,3163.39 5972.44,3224.41 6033.46,3224.41 6033.46,3163.39 5972.44,3163.39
